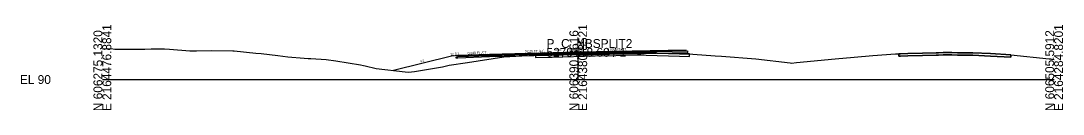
# Model space of a CAD drawing. Extents: x -26 to 1303, y -10 to 12038.
# Drawn here: x -25.7 to 302.8, y -9.7 to 17.3 of the extents above; entities that cross this region are included whole.
import ezdxf

# ---------------------------------------------------------------- set-up
doc = ezdxf.new("R2010")
doc.units = 0
for name, color, linetype in [('RD_GPK_XS_Cell', 7, 'Continuous'), ('RD_XS_Base', 7, 'Continuous'), ('RD_XS_ExGround', 7, 'Continuous'), ('RD_XS_ExPaveRet', 7, 'Continuous'), ('RD_XS_Greenside', 7, 'Continuous'), ('RD_XS_Pave', 7, 'Continuous'), ('RD_XS_PaveOvlay_CP', 7, 'Continuous'), ('RD_XS_TieSlope', 7, 'Continuous'), ('RD_XS_TX_Elev_EX', 7, 'Continuous'), ('RD_XS_TX_Elev_PR', 7, 'Continuous'), ('RD_XS_TX_ShdSlope', 7, 'Continuous'), ('RD_XS_TX_Slope', 7, 'Continuous')]:
    doc.layers.add(name, color=color, linetype=linetype)

msp = doc.modelspace()

# ---------------------------------------------------------------- linework, layer by layer
at = {"layer": 'RD_GPK_XS_Cell'}
for p, q in [((150, 0), (150, 10)), ((0, 0), (150, 0)), ((150, 0), (300, 0))]:
    msp.add_line(p, q, dxfattribs=at)
at = {"layer": 'RD_XS_Base'}
for p, q in [((111.5, 7.22), (112, 7.24)), ((111.5, 6.72), (111.5, 7.22)), ((111.5, 7.22), (111.5, 7.22)), ((112, 6.74), (111.5, 6.72)), ((111.5, 6.72), (111.5, 6.72)), ((111.5, 6.72), (111.5, 6.72)), ((112, 7.24), (122, 7.64)), ((112, 7.24), (112, 7.24)), ((122, 7.14), (112, 6.74)), ((112, 6.74), (112, 6.74)), ((122, 7.64), (150, 8.34)), ((150, 7.84), (122, 7.14)), ((122, 7.64), (122, 7.64)), ((122, 7.14), (122, 7.14)), ((184, 9.02), (150, 8.34)), ((150, 7.84), (184.5, 8.53)), ((150, 8.34), (150, 8.5)), ((150, 8.5), (150, 7.84)), ((150, 8.34), (150, 8.34)), ((150, 8.34), (150, 8.34)), ((150, 8.34), (150, 8.34)), ((150, 8.34), (150, 7.84)), ((150, 7.84), (150, 7.84)), ((150, 7.84), (150, 7.84)), ((150, 7.84), (150, 7.84)), ((184, 9.02), (184, 9.02)), ((184.5, 8.53), (184.5, 9.03)), ((184.5, 9), (184.5, 9)), ((184.5, 8.5), (184.5, 8.5)), ((184.5, 8.5), (184.5, 8.5))]:
    msp.add_line(p, q, dxfattribs=at)
at = {"layer": 'RD_XS_ExGround'}
msp.add_lwpolyline([(0, 9.67), (2.79, 9.78), (3.9, 9.56), (13.41, 9.59), (15.43, 9.69), (19.62, 9.67), (21.12, 9.57), (27.52, 9.07), (29.69, 9.04), (34.33, 9.23), (41.11, 9.06), (41.51, 9.04), (48.35, 8.36), (50.1, 8.19), (55.27, 7.64), (58.5, 7.18), (63.61, 6.74), (64.87, 6.68), (65.72, 6.64), (70.53, 6.35), (73.61, 5.91), (81.41, 4.61), (82.34, 4.48), (82.87, 4.34), (86.32, 3.5), (95.4, 2.42), (96.47, 2.31), (98.4, 2.57), (102.77, 3.25), (107.21, 4.06), (109.36, 4.5), (115.08, 5.39), (126.59, 7.17), (132.21, 7.46), (136.57, 7.69), (141.76, 7.84), (155.34, 8.25), (161.84, 8.39), (164.91, 8.46), (168.72, 8.53), (169.34, 8.56), (170.05, 8.55), (170.77, 8.52), (171.42, 8.49), (181.95, 8.18), (185.1, 8.08), (186.11, 8.01), (193.12, 7.51), (195.12, 7.34), (205.95, 6.5), (216.75, 5.27), (217.21, 5.22), (218.75, 5.36), (230.94, 6.5), (237.01, 7.05), (242.81, 7.56), (249.98, 8.08), (250.76, 8.14), (251.09, 8.17), (251.54, 8.18), (253.86, 8.24), (258.53, 8.37), (262.81, 8.48), (263.5, 8.49), (265.01, 8.51), (266.79, 8.56), (267.78, 8.51), (269.54, 8.48), (272.43, 8.42), (274.34, 8.41), (279.92, 8.19), (286.34, 7.86), (298.48, 6.54), (298.88, 6.5), (299.15, 6.45), (300, 6.33)], dxfattribs=at)
at = {"layer": 'RD_XS_ExPaveRet'}
for points in [[(185.1, 8.08), (181.95, 8.18), (181.95, 8.18), (171.42, 8.49), (170.77, 8.52), (170.77, 8.52), (170.05, 8.55), (170.05, 8.55), (169.34, 8.56), (169.34, 8.56), (169.34, 8.56), (168.72, 8.53), (164.91, 8.46), (164.91, 8.46), (164.91, 8.46), (161.84, 8.39), (161.84, 8.39), (155.34, 8.25), (141.76, 7.84), (141.76, 7.84), (136.57, 7.69), (136.57, 7.69), (136.57, 7.69), (136.57, 6.94), (136.57, 6.94), (136.57, 6.94), (136.57, 6.94), (141.76, 7.09), (141.76, 7.09), (155.34, 7.5), (161.84, 7.64), (161.84, 7.64), (164.91, 7.71), (164.91, 7.71), (164.91, 7.71), (168.72, 7.78), (169.34, 7.81), (169.34, 7.81), (169.34, 7.81), (170.05, 7.8), (170.05, 7.8), (170.77, 7.77), (170.77, 7.77), (171.42, 7.74), (181.95, 7.43), (181.95, 7.43), (185.1, 7.33), (185.1, 7.33), (185.1, 7.33), (185.1, 8.08), (185.1, 8.08)], [(185.1, 8.08), (181.95, 8.18), (171.42, 8.49), (170.77, 8.52), (170.05, 8.55), (169.34, 8.56), (168.72, 8.53), (164.91, 8.46), (161.84, 8.39), (155.34, 8.25), (141.76, 7.84), (136.57, 7.69), (136.57, 7.69), (136.57, 6.94), (136.57, 6.94), (141.76, 7.09), (155.34, 7.5), (161.84, 7.64), (164.91, 7.71), (168.72, 7.78), (169.34, 7.81), (170.05, 7.8), (170.77, 7.77), (171.42, 7.74), (181.95, 7.43), (185.1, 7.33), (185.1, 7.33), (185.1, 8.08), (185.1, 8.08)], [(286.34, 7.86), (286.34, 7.86), (286.34, 7.86), (286.34, 7.11), (286.34, 7.11), (279.92, 7.44), (274.34, 7.66), (274.34, 7.66), (272.43, 7.67), (272.43, 7.67), (269.54, 7.73), (269.54, 7.73), (267.78, 7.76), (267.78, 7.76), (266.79, 7.81), (266.79, 7.81), (266.79, 7.81), (265.01, 7.76), (265.01, 7.76), (263.5, 7.74), (263.5, 7.74), (262.81, 7.73), (258.53, 7.62), (258.53, 7.62), (253.86, 7.49), (253.86, 7.49), (251.54, 7.43), (251.09, 7.42), (251.09, 7.42), (251.09, 7.42), (251.09, 8.17), (251.09, 8.17), (251.54, 8.18), (253.86, 8.24), (253.86, 8.24), (258.53, 8.37), (258.53, 8.37), (262.81, 8.48), (263.5, 8.49), (263.5, 8.49), (265.01, 8.51), (265.01, 8.51), (266.79, 8.56), (266.79, 8.56), (266.79, 8.56), (267.78, 8.51), (267.78, 8.51), (269.54, 8.48), (269.54, 8.48), (272.43, 8.42), (272.43, 8.42), (274.34, 8.41), (274.34, 8.41), (279.92, 8.19), (286.34, 7.86)], [(279.92, 8.19), (274.34, 8.41), (272.43, 8.42), (269.54, 8.48), (267.78, 8.51), (266.79, 8.56), (265.01, 8.51), (263.5, 8.49), (262.81, 8.48), (258.53, 8.37), (253.86, 8.24), (251.54, 8.18), (251.09, 8.17), (251.09, 7.42), (251.54, 7.43), (253.86, 7.49), (258.53, 7.62), (262.81, 7.73), (263.5, 7.74), (265.01, 7.76), (266.79, 7.81), (267.78, 7.76), (269.54, 7.73), (272.43, 7.67), (274.34, 7.66), (279.92, 7.44), (286.34, 7.11), (286.34, 7.86), (279.92, 8.19)]]:
    msp.add_lwpolyline(points, dxfattribs=at)
at = {"layer": 'RD_XS_Greenside'}
msp.add_line((110, 7.4), (91.78, 2.85), dxfattribs=at)
at = {"layer": 'RD_XS_Pave'}
for p, q in [((122, 7.96), (112, 7.56)), ((122, 7.8), (112, 7.4)), ((112, 7.4), (122, 7.8)), ((112, 7.24), (122, 7.64)), ((112, 7.56), (112, 7.56)), ((112, 7.56), (112, 7.4)), ((112, 7.4), (112, 7.4)), ((112, 7.4), (112, 7.24)), ((112, 7.4), (112, 7.4)), ((112, 7.4), (112, 7.4)), ((112, 7.24), (112, 7.24)), ((112, 7.24), (112, 7.24)), ((150, 8.66), (122, 7.96)), ((150, 8.5), (122, 7.8)), ((122, 7.8), (150, 8.5)), ((122, 7.64), (150, 8.34)), ((122, 7.96), (122, 7.96)), ((122, 7.8), (122, 7.8)), ((122, 7.8), (122, 7.8)), ((122, 7.64), (122, 7.64)), ((184, 9.34), (150, 8.66)), ((184, 9.18), (150, 8.5)), ((150, 8.5), (184, 9.18)), ((150, 8.34), (184.5, 9.03)), ((150, 8.66), (150, 8.66)), ((150, 8.34), (150, 8.5)), ((150, 8.5), (150, 8.5)), ((150, 8.5), (150, 8.5)), ((150, 8.5), (150, 8.34)), ((150, 8.5), (150, 8.5)), ((150, 8.34), (150, 8.34)), ((150, 8.34), (150, 8.34)), ((150, 8.34), (150, 8.34)), ((150, 8.34), (150, 8.34)), ((184, 9.18), (184, 9.34)), ((184, 9.34), (184, 9.34)), ((184, 9.02), (184, 9.18)), ((184, 9.18), (184, 9.18)), ((184, 9.18), (184, 9.18)), ((184, 9.18), (184, 9.18)), ((184, 9.02), (184, 9.02)), ((184, 9.02), (184, 9.02))]:
    msp.add_line(p, q, dxfattribs=at)
at = {"layer": 'RD_XS_PaveOvlay_CP'}
for p, q in [((122, 7.96), (112, 7.56)), ((112, 7.56), (112, 7.56)), ((150, 8.66), (122, 7.96)), ((122, 7.96), (122, 7.96)), ((184, 9.34), (150, 8.66)), ((150, 8.66), (150, 8.66)), ((184, 9.34), (184, 9.34))]:
    msp.add_line(p, q, dxfattribs=at)
at = {"layer": 'RD_XS_TieSlope'}
msp.add_line((112, 7.56), (110, 7.4), dxfattribs=at)

# ---------------------------------------------------------------- texts
at = {"layer": 'RD_GPK_XS_Cell'}
for s, p in [('E 2164476.8841', (2.8, -10)), ('E 2164380.8521', (152.8, -10)), ('E 2164284.8201', (302.8, -10)), ('N 606275.1320', (0, -10)), ('N 606390.3616', (150, -10)), ('N 606505.5912', (300, -10))]:
    msp.add_text(s, height=2.8, rotation=90, dxfattribs=at).set_placement(p)
for s, p in [('5279+18.60 / 1', (140, 7.2)), ('P_C_NBSPLIT2', (140, 10)), ('EL 90', (-26, -1.4))]:
    msp.add_text(s, height=2.8, dxfattribs=at).set_placement(p)
at = {"layer": 'RD_XS_TX_Elev_EX'}
msp.add_text('98.09', height=0.6, rotation=90, dxfattribs=at).set_placement((149.61, 9.38))
at = {"layer": 'RD_XS_TX_Elev_PR'}
msp.add_text('98.66', height=1, rotation=90, dxfattribs=at).set_placement((151.32, 8.86))
at = {"layer": 'RD_XS_TX_ShdSlope'}
msp.add_text('12.5:1', height=0.75, rotation=4.5739, dxfattribs=at).set_placement((109.66, 7.61))
at = {"layer": 'RD_XS_TX_Slope'}
for s, rotation, p in [('0.020 FT./FT.', 1.1458, (159.15, 9.11)), ('0.040 FT./FT.', 2.2906, (115.14, 7.95)), ('0.025 FT./FT.', 1.4321, (133.14, 8.5)), ('4:1', 14.0362, (100.2, 5.39))]:
    msp.add_text(s, height=0.75, rotation=rotation, dxfattribs=at).set_placement(p)

doc.saveas('drawing.dxf')
